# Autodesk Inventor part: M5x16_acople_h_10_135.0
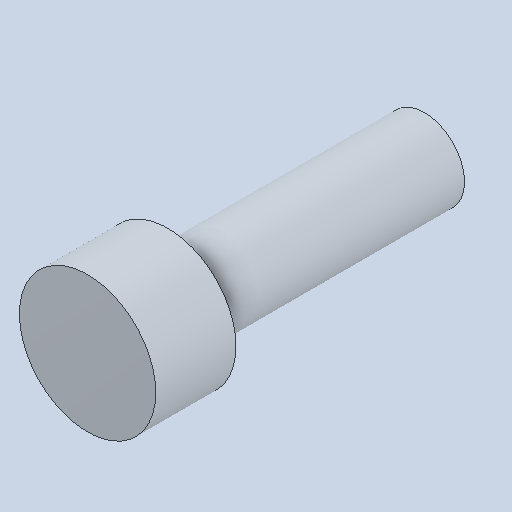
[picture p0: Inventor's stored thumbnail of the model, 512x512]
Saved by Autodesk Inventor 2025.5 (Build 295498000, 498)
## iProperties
Created: 2026-10
Part Number: M5x16_acople_h_10_135.0
Material: Genérico
Document SubType Name: Modeling
Designer: Luis M
Density: 1 g/cm^3
Appearance: Valor por defecto
Author: Luis M
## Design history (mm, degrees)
feature "Base1"
node "Sólido1"
